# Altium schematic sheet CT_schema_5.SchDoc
size 297 x 173 mm
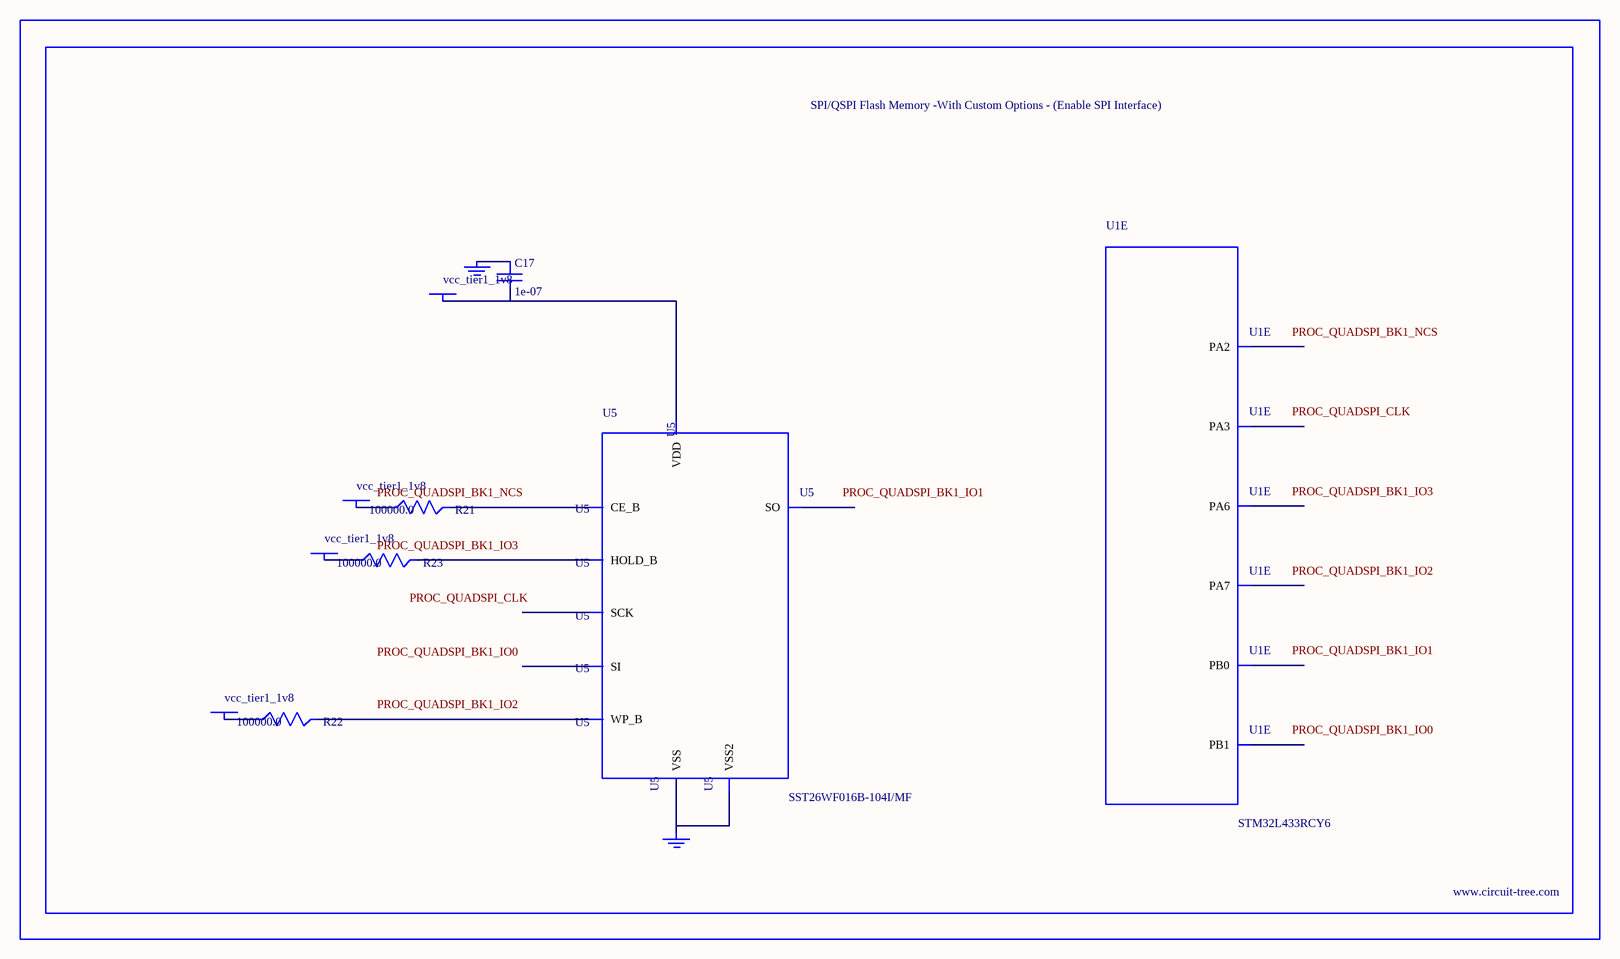
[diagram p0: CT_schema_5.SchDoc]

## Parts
BORDER4  (no value)
C17  1e-07  [C0402]
GND_INSTANCE_4_0  (no value)
GND_INSTANCE_4_1  (no value)
POWER_INSTANCE_4_0  vcc_tier1_1v8
POWER_INSTANCE_4_1  vcc_tier1_1v8
POWER_INSTANCE_4_2  vcc_tier1_1v8
POWER_INSTANCE_4_3  vcc_tier1_1v8
R21  100000.0  [R0603]
R22  100000.0  [R0603]
R23  100000.0  [R0603]
U1  STM32L433RCY6  [WLCSP64]  (part E of 8)
U5  SST26WF016B-104I/MF  [WFDN-8]

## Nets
NetC17_1: C17.1 GND_INSTANCE_4_0.0(GND)
NetC17_2: C17.2 POWER_INSTANCE_4_3.0(PWR) U5.8(VDD)
NetGND_INSTANCE_4_1_0: GND_INSTANCE_4_1.0(GND) U5.4(VSS) U5.9(VSS2)
NetPOWER_INSTANCE_4_0_0: POWER_INSTANCE_4_0.0(PWR) R21.1
NetPOWER_INSTANCE_4_1_0: POWER_INSTANCE_4_1.0(PWR) R22.1
NetPOWER_INSTANCE_4_2_0: POWER_INSTANCE_4_2.0(PWR) R23.1
NetR21_2: R21.2 U5.1(CE_B)
NetR22_2: R22.2 U5.3(WP_B)
NetR23_2: R23.2 U5.7(HOLD_B)

Not connected (* = marked no-connect by the designer): U1 F4(PB0) F6(PA2) G5(PA6) G6(PA3) H5(PB1) H6(PA7); U5 2(SO) 5(SI) 6(SCK)

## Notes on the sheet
- Labels drawn without touching a wire or pin: PROC_QUADSPI_BK1_IO0, PROC_QUADSPI_BK1_IO1, PROC_QUADSPI_BK1_IO2, PROC_QUADSPI_BK1_IO3, PROC_QUADSPI_BK1_NCS, PROC_QUADSPI_CLK

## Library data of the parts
BORDER4 = BORDER_PAGE4
C17 = C0402C104K3RACTU
GND_INSTANCE_4_0 GND_INSTANCE_4_1 = GND
POWER_INSTANCE_4_0-POWER_INSTANCE_4_3 = PWR
R21-R23 = RC0603JR-07100KL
